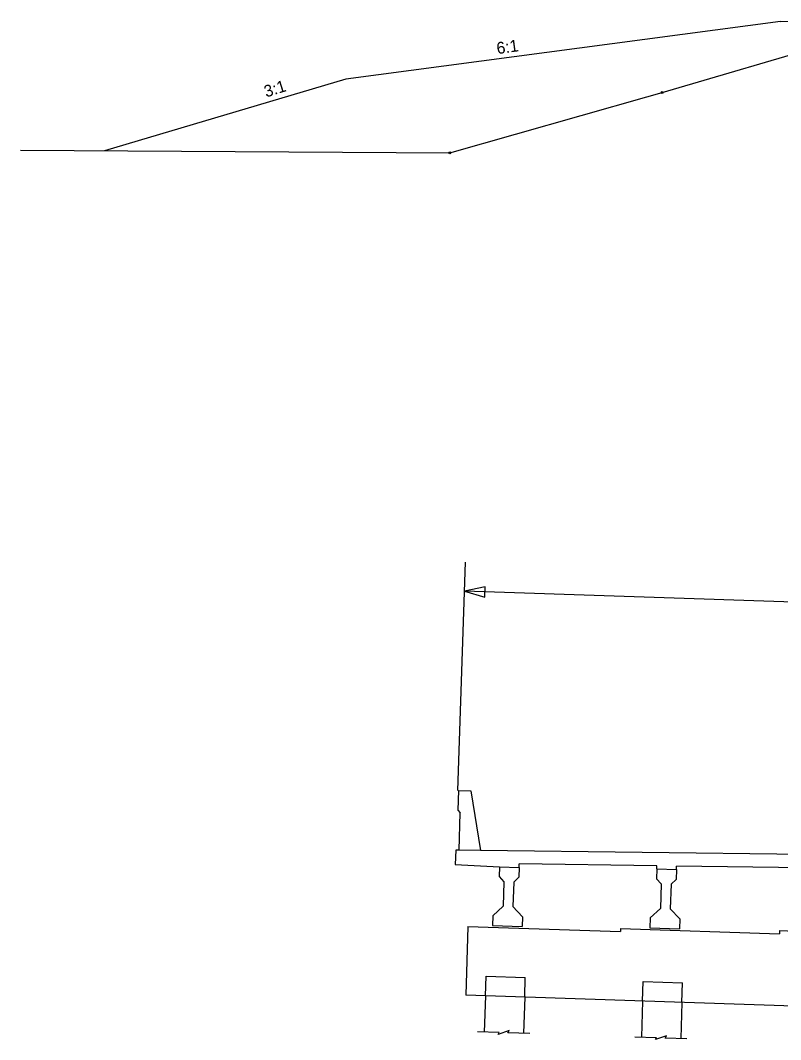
# Model space of a CAD drawing. Extents: x 977258 to 978774, y 1525946 to 1526932.
# Drawn here: x 977258 to 977645, y 1526219 to 1526738 of the extents above; entities that cross this region are included whole.
import ezdxf

# ---------------------------------------------------------------- set-up
doc = ezdxf.new("R2010")
doc.units = 0
for name, color, linetype in [('B_border', 7, 'Continuous'), ('B_Preliminary', 7, 'Continuous'), ('B_Print_Date_Text', 7, 'Continuous'), ('BDR_Plan Profile Grid 1', 7, 'Continuous'), ('BDR_Plan Profile Grid 5', 7, 'Continuous'), ('BDR_Plan Profile Grid 6', 7, 'Continuous'), ('R_Border', 7, 'Continuous'), ('STAMP_PP', 7, 'Continuous')]:
    doc.layers.add(name, color=color, linetype=linetype)

msp = doc.modelspace()

# ---------------------------------------------------------------- linework, layer by layer
at = {"layer": 'B_border'}
for centre in [(977584.62, 1526700.89), (977476.71, 1526670.18)]:
    msp.add_circle(centre, 0.5, dxfattribs=at)
at = {"layer": 'B_Preliminary'}
msp.add_lwpolyline([(977258.38, 1526671.55), (977476.71, 1526670.18), (977576.91, 1526698.71), (977584.62, 1526700.89), (977590.5, 1526702.57), (977665.58, 1526724.58), (977683.24, 1526725.62), (977712.46, 1526727.47), (977716.28, 1526727.8), (977731.73, 1526730.1), (977748.57, 1526729.75), (977829.7, 1526727.99), (977917.45, 1526721.89), (977932.64, 1526720.78), (977944.35, 1526720.32), (977945.99, 1526720.26), (977965.72, 1526714.93), (977981.46, 1526710.71), (978040.15, 1526692.86), (978045.03, 1526691.56), (978057.39, 1526687.35), (978143.72, 1526659.23), (978205.08, 1526651.49), (978261.1, 1526644)], dxfattribs=at)
at = {"layer": 'B_Print_Date_Text'}
for p, q in [((977644.9, 1526736.99), (977423.8, 1526707.68)), ((977644.9, 1526736.99), (977724.96, 1526737.52)), ((977423.8, 1526707.68), (977301.14, 1526671.28))]:
    msp.add_line(p, q, dxfattribs=at)
at = {"layer": 'BDR_Plan Profile Grid 1'}
for p, q in [((977501.78, 1526223.07), (977490.84, 1526223.43)), ((977506.97, 1526224.01), (977501.36, 1526222.12)), ((977501.36, 1526222.12), (977501.78, 1526223.07)), ((977506.27, 1526222.92), (977506.97, 1526224.01)), ((977517.33, 1526222.55), (977506.27, 1526222.92)), ((977581.73, 1526220.4), (977570.8, 1526220.76)), ((977586.93, 1526221.35), (977581.32, 1526219.45)), ((977586.22, 1526220.25), (977586.93, 1526221.35)), ((977581.32, 1526219.45), (977581.73, 1526220.4)), ((977597.29, 1526219.88), (977586.22, 1526220.25))]:
    msp.add_line(p, q, dxfattribs=at)
at = {"layer": 'BDR_Plan Profile Grid 5'}
for p, q in [((977481.17, 1526346.04), (977480.84, 1526336.05)), ((977481.17, 1526346.04), (977487.42, 1526345.83)), ((977487.42, 1526345.83), (977492.25, 1526315.66)), ((977480.84, 1526336.05), (977482.05, 1526334.76)), ((977481.41, 1526315.8), (977482.05, 1526334.76)), ((977479.75, 1526315.82), (977479.5, 1526308.54)), ((977481.41, 1526315.8), (977479.75, 1526315.82)), ((977867.29, 1526310.65), (977492.25, 1526315.66)), ((977511.97, 1526306.96), (977512.03, 1526308.73)), ((977582.03, 1526307.79), (977512.03, 1526308.73)), ((977479.5, 1526308.54), (977501.97, 1526307.29)), ((977501.97, 1526307.29), (977501.81, 1526302.3)), ((977501.97, 1526307.29), (977501.81, 1526302.3)), ((977501.97, 1526307.29), (977511.97, 1526306.96)), ((977501.97, 1526307.29), (977511.97, 1526306.96)), ((977511.97, 1526306.96), (977511.8, 1526301.96)), ((977511.97, 1526306.96), (977511.8, 1526301.96)), ((977511.97, 1526306.96), (977511.8, 1526301.96)), ((977511.97, 1526306.96), (977511.8, 1526301.96)), ((977581.98, 1526306.23), (977581.81, 1526301.23)), ((977581.98, 1526306.23), (977581.81, 1526301.23)), ((977581.98, 1526306.23), (977582.03, 1526307.79)), ((977581.98, 1526306.23), (977591.98, 1526305.89)), ((977581.98, 1526306.23), (977591.98, 1526305.89)), ((977591.98, 1526305.89), (977591.81, 1526300.9)), ((977591.98, 1526305.89), (977591.81, 1526300.9)), ((977591.98, 1526305.89), (977591.81, 1526300.9)), ((977591.98, 1526305.89), (977591.81, 1526300.9)), ((977591.98, 1526305.89), (977592.03, 1526307.66)), ((977662.04, 1526306.73), (977592.03, 1526307.66)), ((977501.81, 1526302.3), (977504.22, 1526299.72)), ((977501.81, 1526302.3), (977504.22, 1526299.72)), ((977504.22, 1526299.72), (977503.8, 1526287.22)), ((977504.22, 1526299.72), (977503.8, 1526287.22)), ((977509.22, 1526299.55), (977508.8, 1526287.06)), ((977509.22, 1526299.55), (977508.8, 1526287.06)), ((977511.8, 1526301.96), (977509.22, 1526299.55)), ((977511.8, 1526301.96), (977509.22, 1526299.55)), ((977581.81, 1526301.23), (977584.23, 1526298.65)), ((977581.81, 1526301.23), (977584.23, 1526298.65)), ((977584.23, 1526298.65), (977583.81, 1526286.16)), ((977584.23, 1526298.65), (977583.81, 1526286.16)), ((977589.23, 1526298.48), (977588.81, 1526285.99)), ((977589.23, 1526298.48), (977588.81, 1526285.99)), ((977591.81, 1526300.9), (977589.23, 1526298.48)), ((977591.81, 1526300.9), (977589.23, 1526298.48)), ((977498.64, 1526282.39), (977503.8, 1526287.22)), ((977498.64, 1526282.39), (977503.8, 1526287.22)), ((977513.63, 1526281.89), (977508.8, 1526287.06)), ((977513.63, 1526281.89), (977508.8, 1526287.06)), ((977578.65, 1526281.32), (977583.81, 1526286.16)), ((977578.65, 1526281.32), (977583.81, 1526286.16)), ((977593.64, 1526280.82), (977588.81, 1526285.99)), ((977593.64, 1526280.82), (977588.81, 1526285.99)), ((977498.64, 1526282.39), (977498.47, 1526277.39)), ((977498.64, 1526282.39), (977498.47, 1526277.39)), ((977513.63, 1526281.89), (977513.47, 1526276.89)), ((977513.63, 1526281.89), (977513.47, 1526276.89)), ((977578.65, 1526281.32), (977578.48, 1526276.33)), ((977578.65, 1526281.32), (977578.48, 1526276.33)), ((977593.64, 1526280.82), (977593.47, 1526275.83)), ((977593.64, 1526280.82), (977593.47, 1526275.83)), ((977485.95, 1526276.98), (977484.79, 1526242)), ((977485.95, 1526276.98), (977563.41, 1526274.4)), ((977498.47, 1526277.39), (977513.47, 1526276.89)), ((977498.47, 1526277.39), (977513.47, 1526276.89)), ((977563.47, 1526275.99), (977563.41, 1526274.4)), ((977563.47, 1526275.99), (977644.25, 1526273.3)), ((977578.48, 1526276.33), (977593.47, 1526275.83)), ((977578.48, 1526276.33), (977593.47, 1526275.83)), ((977644.31, 1526274.9), (977644.25, 1526273.3)), ((977644.31, 1526274.9), (977725.1, 1526272.21)), ((977884.56, 1526228.67), (977484.79, 1526242)), ((977494.78, 1526241.66), (977494.17, 1526223.32)), ((977514.77, 1526241), (977514.16, 1526222.65)), ((977574.74, 1526239), (977574.13, 1526220.65)), ((977594.73, 1526238.33), (977594.11, 1526219.99))]:
    msp.add_line(p, q, dxfattribs=at)
at = {"layer": 'BDR_Plan Profile Grid 6'}
for p, q in [((977492.25, 1526315.66), (977481.41, 1526315.8)), ((977494.78, 1526241.66), (977495.11, 1526251.66)), ((977495.11, 1526251.66), (977515.1, 1526250.99)), ((977514.77, 1526241), (977515.1, 1526250.99)), ((977574.74, 1526239), (977575.07, 1526248.99)), ((977575.07, 1526248.99), (977595.06, 1526248.33)), ((977594.73, 1526238.33), (977595.06, 1526248.33))]:
    msp.add_line(p, q, dxfattribs=at)
at = {"layer": 'STAMP_PP'}
for p, q in [((977480.75, 1526346.06), (977484.63, 1526462.2)), ((977890.07, 1526433.83), (977484.13, 1526447.37))]:
    msp.add_line(p, q, dxfattribs=at)
msp.add_lwpolyline([(977494.77, 1526449.65), (977484.13, 1526447.37), (977494.6, 1526444.38)], close=True, dxfattribs=at)

# ---------------------------------------------------------------- texts
at = {"layer": 'R_Border'}
for s, rotation, p in [('6:1', 7.7588, (977500.88, 1526720.35)), ('3:1', 17.4294, (977383.33, 1526698.32))]:
    msp.add_text(s, height=6, rotation=rotation, dxfattribs=at).set_placement(p)

doc.saveas('drawing.dxf')
